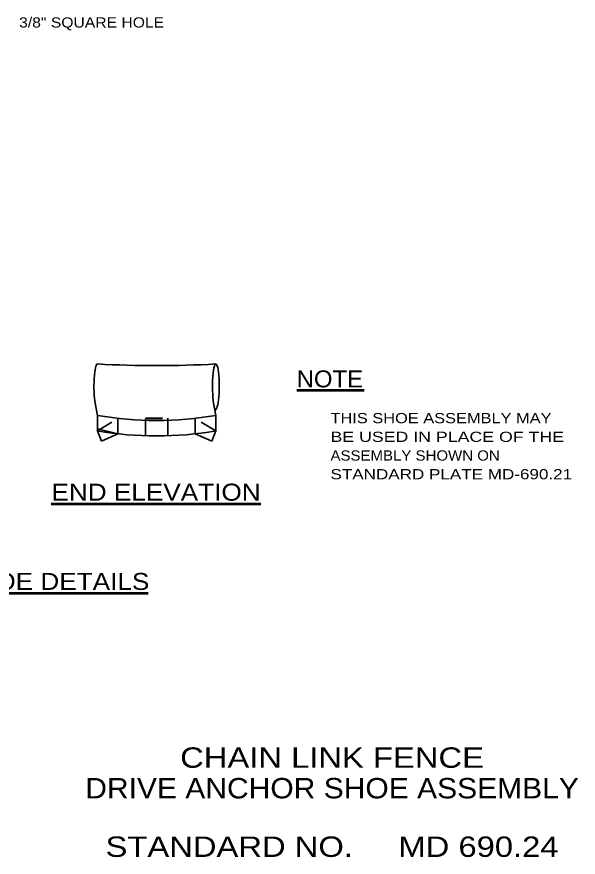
# Model space of a CAD drawing. Extents: x -38.29 to -31.67, y 88.17 to 97.95.
# Drawn here: x -35.47 to -32.168, y 88.172 to 93.115 of the extents above; entities that cross this region are included whole.
import ezdxf
from ezdxf.enums import TextEntityAlignment as Align

# ---------------------------------------------------------------- set-up
doc = ezdxf.new("R2010")
doc.units = 0
doc.header["$LTSCALE"] = 0.024
doc.linetypes.add('SHORT_DASHED', pattern=[2.7, 1.5, -1.2])
for name, color, linetype, lineweight in [('1', 7, 'Continuous', 35), ('12', 7, 'Continuous', 53), ('13', 7, 'Continuous', 53)]:
    doc.layers.add(name, color=color, linetype=linetype, lineweight=lineweight)

msp = doc.modelspace()

# ---------------------------------------------------------------- linework, layer by layer
at = {"layer": '1'}
for p, q in [((-35.00927, 90.84192), (-34.99627, 90.77112)), ((-34.31231, 90.84192), (-34.29931, 90.77112)), ((-34.29435, 90.81521), (-34.30438, 90.79877)), ((-34.99627, 90.68021), (-34.99627, 90.77112)), ((-34.29931, 90.77112), (-34.29931, 90.68021)), ((-34.99627, 90.69202), (-34.87506, 90.66273)), ((-34.99627, 90.68021), (-34.97242, 90.6196)), ((-34.87506, 90.66273), (-34.97242, 90.6196)), ((-34.42052, 90.66273), (-34.32317, 90.6196)), ((-34.29931, 90.68021), (-34.32317, 90.6196))]:
    msp.add_line(p, q, dxfattribs=at)
at = {"layer": '1', "linetype": 'SHORT_DASHED'}
for p, q in [((-34.71346, 90.65098), (-34.71346, 90.75492)), ((-34.71346, 90.75492), (-34.58215, 90.75492)), ((-34.71346, 90.74187), (-34.58215, 90.74187)), ((-34.58215, 90.75492), (-34.58215, 90.65098))]:
    msp.add_line(p, q, dxfattribs=at)
for points in [[(-34.99627, 90.68021), (-34.87506, 90.75365), (-34.87506, 90.66273)], [(-34.29931, 90.68021), (-34.42052, 90.75365), (-34.42052, 90.66273)]]:
    msp.add_lwpolyline(points, dxfattribs=at)
at = {"layer": '1'}
for centre, radius, start, end in [((-34.64779, 97.39036), 6.32673, 266.84247, 273.15753), ((-34.64779, 92.75975), 2.01894, 260.06052, 279.93948), ((-34.64779, 92.66884), 2.01894, 260.06052, 279.93948)]:
    msp.add_arc(centre, radius, start, end, dxfattribs=at)
for centre, start_param in [((-34.99613, 90.94223), 3.1159199), ((-34.29931, 90.94223), 0.2478042)]:
    msp.add_ellipse(centre, major_axis=(0, -0.13101), ratio=0.154202, start_param=start_param, end_param=5.5843813, dxfattribs=at)
at = {"layer": '12'}
for p, q in [((-35.26808, 90.25069), (-34.03446, 90.25069)), ((-36.51812, 89.72554), (-34.69712, 89.72554))]:
    msp.add_line(p, q, dxfattribs=at)
at = {"layer": '13'}
msp.add_line((-33.82377, 90.91846), (-33.42633, 90.91846), dxfattribs=at)

# ---------------------------------------------------------------- texts
at = {"layer": '12', "width": 1.15}
msp.add_text('3/8" SQUARE HOLE', height=0.06, dxfattribs=at).set_placement((-35.45683, 93.05226))
for s, p in [('END ELEVATION', (-34.65126, 90.26928)), ('ANCHOR SHOE DETAILS', (-35.60499, 89.74415))]:
    msp.add_text(s, height=0.1, dxfattribs=at).set_placement(p, align=Align.CENTER)
at = {"layer": '13'}
for s, height, width, p in [('NOTE', 0.1, 1.05, (-33.82376, 90.93555)), ('THIS SHOE ASSEMBLY MAY', 0.06, 1.2, (-33.62504, 90.72495)), ('BE USED IN PLACE OF THE', 0.06, 1.3, (-33.62504, 90.61495)), ('ASSEMBLY SHOWN ON', 0.06, 1.1, (-33.62504, 90.50495)), ('STANDARD PLATE MD-690.21', 0.06, 1.25, (-33.62504, 90.39495))]:
    msp.add_text(s, height=height, dxfattribs=dict(at, width=width)).set_placement(p)
for s, width, p in [('CHAIN LINK FENCE', 1.2, (-33.61589, 88.69804)), ('DRIVE ANCHOR SHOE ASSEMBLY', 1.1, (-33.61589, 88.51804)), ('STANDARD NO.     MD 690.24', 1.2, (-33.61589, 88.17386))]:
    msp.add_text(s, height=0.12, dxfattribs=dict(at, width=width)).set_placement(p, align=Align.CENTER)

doc.saveas('drawing.dxf')
